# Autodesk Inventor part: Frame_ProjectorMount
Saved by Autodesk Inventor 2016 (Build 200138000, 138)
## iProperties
Created: 2015-11
Part Number: Frame_ProjectorMount
Material: Generic
Document SubType Name: Modeling
Designer: John
Density: 1 g/cm^3
Appearance: Default
Author: John
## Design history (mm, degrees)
feature "SOLID1"
body "Solid1"
